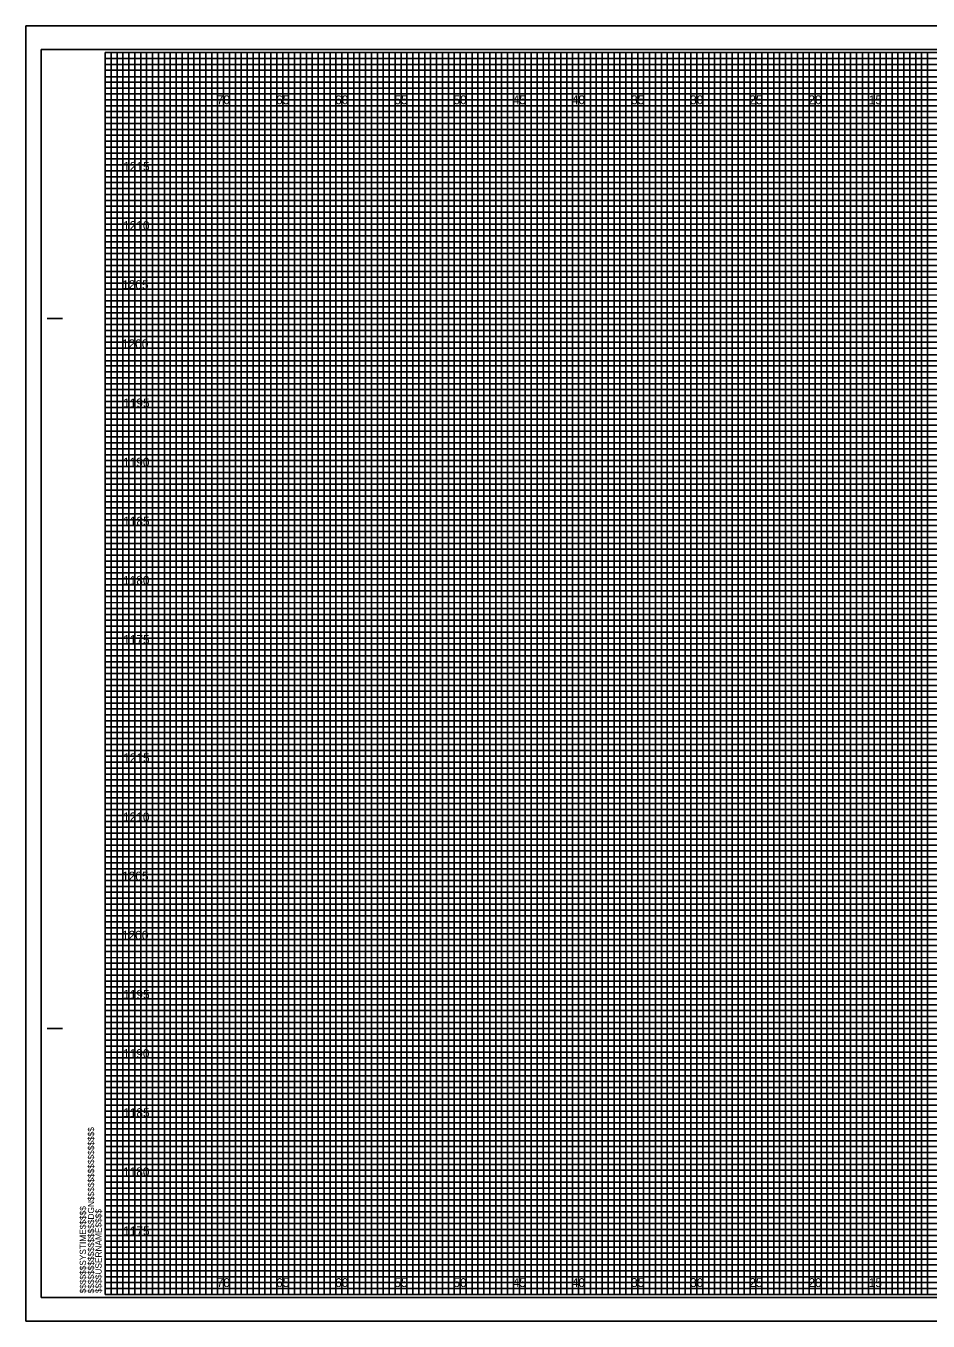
# Model space of a CAD drawing. Extents: x 3478 to 3647, y -9 to 1255.
# Drawn here: x 3478.3 to 3554.6, y 650.7 to 760.2 of the extents above; entities that cross this region are included whole.
import ezdxf

# ---------------------------------------------------------------- set-up
doc = ezdxf.new("R2010")
doc.units = 0
for name, color, linetype in [('Exist Cross Section Cell', 7, 'Continuous'), ('Prop CMT Subgrade Earthwork', 7, 'Continuous'), ('Prop Conc 4in Sidewalk', 7, 'Continuous'), ('Prop Conc Island Cover', 7, 'Continuous'), ('Sheet Cross Section CELL', 7, 'Continuous'), ('Sheet Cross Section Grid Minor 1 CELL', 7, 'Continuous'), ('Sheet Cross Section Grid Minor 2 CELL', 7, 'Continuous'), ('Sheet Cutting Line CELL', 7, 'Continuous'), ('Sheet DOT Grid CELL', 7, 'Continuous'), ('Sheet Plot Border Inside CELL', 7, 'Continuous')]:
    doc.layers.add(name, color=color, linetype=linetype)

msp = doc.modelspace()

# ---------------------------------------------------------------- linework, layer by layer
at = {"layer": 'Exist Cross Section Cell'}
for points in [[(3485.01, 757.97), (3487.51, 757.97), (3487.51, 652.97), (3492.51, 652.97), (3492.51, 757.97), (3497.51, 757.97), (3497.51, 652.97), (3502.51, 652.97), (3502.51, 757.97), (3507.51, 757.97), (3507.51, 652.97), (3512.51, 652.97), (3512.51, 757.97), (3517.51, 757.97), (3517.51, 652.97), (3522.51, 652.97), (3522.51, 757.97), (3527.51, 757.97), (3527.51, 652.97), (3532.51, 652.97), (3532.51, 757.97), (3537.51, 757.97), (3537.51, 652.97), (3542.51, 652.97), (3542.51, 757.97), (3547.51, 757.97), (3547.51, 652.97), (3552.51, 652.97), (3552.51, 757.97), (3557.51, 757.97)], [(3485.01, 755.47), (3622.51, 755.47)], [(3485.01, 745.47), (3645.01, 745.47), (3645.01, 750.47), (3485.01, 750.47)], [(3485.01, 735.47), (3645.01, 735.47), (3645.01, 740.47), (3485.01, 740.47)], [(3485.01, 725.47), (3645.01, 725.47), (3645.01, 730.47), (3485.01, 730.47)], [(3485.01, 715.47), (3645.01, 715.47), (3645.01, 720.47), (3485.01, 720.47)], [(3485.01, 705.47), (3645.01, 705.47), (3645.01, 710.47), (3485.01, 710.47)], [(3485.01, 695.47), (3645.01, 695.47), (3645.01, 700.47), (3485.01, 700.47)], [(3485.01, 685.47), (3645.01, 685.47), (3645.01, 690.47), (3485.01, 690.47)], [(3485.01, 675.47), (3645.01, 675.47), (3645.01, 680.47), (3485.01, 680.47)], [(3485.01, 665.47), (3645.01, 665.47), (3645.01, 670.47), (3485.01, 670.47)], [(3485.01, 655.47), (3645.01, 655.47), (3645.01, 660.47), (3485.01, 660.47)]]:
    msp.add_lwpolyline(points, dxfattribs=at)
at = {"layer": 'Prop CMT Subgrade Earthwork'}
msp.add_lwpolyline([(3478.31, 650.72), (3646.66, 650.72), (3646.66, 760.22), (3478.31, 760.22)], close=True, dxfattribs=at)
at = {"layer": 'Prop Conc 4in Sidewalk'}
for p, q in [((3490.01, 757.97), (3485.01, 757.97)), ((3490.01, 652.97), (3490.01, 757.97)), ((3500.01, 757.97), (3495.01, 757.97)), ((3495.01, 757.97), (3495.01, 652.97)), ((3500.01, 652.97), (3500.01, 757.97)), ((3510.01, 757.97), (3505.01, 757.97)), ((3505.01, 757.97), (3505.01, 652.97)), ((3510.01, 652.97), (3510.01, 757.97)), ((3520.01, 757.97), (3515.01, 757.97)), ((3515.01, 757.97), (3515.01, 652.97)), ((3520.01, 652.97), (3520.01, 757.97)), ((3530.01, 757.97), (3525.01, 757.97)), ((3525.01, 757.97), (3525.01, 652.97)), ((3530.01, 652.97), (3530.01, 757.97)), ((3540.01, 757.97), (3535.01, 757.97)), ((3535.01, 757.97), (3535.01, 652.97)), ((3540.01, 652.97), (3540.01, 757.97)), ((3550.01, 757.97), (3545.01, 757.97)), ((3545.01, 757.97), (3545.01, 652.97)), ((3550.01, 652.97), (3550.01, 757.97)), ((3495.01, 652.97), (3490.01, 652.97)), ((3505.01, 652.97), (3500.01, 652.97)), ((3515.01, 652.97), (3510.01, 652.97)), ((3525.01, 652.97), (3520.01, 652.97)), ((3535.01, 652.97), (3530.01, 652.97)), ((3545.01, 652.97), (3540.01, 652.97)), ((3555.01, 652.97), (3550.01, 652.97))]:
    msp.add_line(p, q, dxfattribs=at)
for points in [[(3485.01, 752.97), (3645.01, 752.97), (3645.01, 747.97), (3485.01, 747.97)], [(3485.01, 742.97), (3645.01, 742.97), (3645.01, 737.97), (3485.01, 737.97)], [(3485.01, 732.97), (3645.01, 732.97), (3645.01, 727.97), (3485.01, 727.97)], [(3485.01, 722.97), (3645.01, 722.97), (3645.01, 717.97), (3485.01, 717.97)], [(3485.01, 712.97), (3645.01, 712.97), (3645.01, 707.97), (3485.01, 707.97)], [(3485.01, 702.97), (3645.01, 702.97), (3645.01, 697.97), (3485.01, 697.97)], [(3485.01, 692.97), (3645.01, 692.97), (3645.01, 687.97), (3485.01, 687.97)], [(3485.01, 682.97), (3645.01, 682.97), (3645.01, 677.97), (3485.01, 677.97)], [(3485.01, 672.97), (3645.01, 672.97), (3645.01, 667.97), (3485.01, 667.97)], [(3485.01, 662.97), (3645.01, 662.97), (3645.01, 657.97), (3485.01, 657.97)]]:
    msp.add_lwpolyline(points, dxfattribs=at)
at = {"layer": 'Sheet Cross Section CELL'}
for p, q in [((3480.11, 735.47), (3481.36, 735.47)), ((3480.16, 735.47), (3481.41, 735.47)), ((3480.11, 675.47), (3481.36, 675.47)), ((3480.16, 675.47), (3481.41, 675.47))]:
    msp.add_line(p, q, dxfattribs=at)
msp.add_lwpolyline([(3645.01, 757.97), (3485.01, 757.97), (3485.01, 652.97), (3645.01, 652.97)], close=True, dxfattribs=at)
at = {"layer": 'Sheet Cross Section Grid Minor 1 CELL'}
for p, q in [((3485.01, 757.47), (3615.01, 757.47)), ((3615.01, 756.96), (3485.01, 756.96)), ((3485.01, 756.96), (3485.01, 756.47)), ((3485.01, 756.47), (3615.01, 756.47)), ((3615.01, 755.92), (3485.01, 755.92)), ((3485.01, 755.92), (3485.01, 754.97)), ((3485.01, 754.97), (3645.01, 754.97))]:
    msp.add_line(p, q, dxfattribs=at)
for points in [[(3485.01, 754.47), (3620.01, 754.47), (3645.01, 754.47), (3645.01, 753.97), (3485.01, 753.97)], [(3485.01, 753.47), (3645.01, 753.47), (3645.01, 752.47), (3485.01, 752.47)], [(3485.01, 751.97), (3645.01, 751.97), (3645.01, 751.47), (3485.01, 751.46)], [(3485.01, 750.97), (3645.01, 750.97), (3645.01, 749.97), (3485.01, 749.97)], [(3485.01, 749.47), (3645.01, 749.47), (3645.01, 748.97), (3485.01, 748.97)], [(3485.01, 748.47), (3645.01, 748.47), (3645.01, 747.47), (3485.01, 747.47)], [(3485.01, 746.97), (3645.01, 746.97), (3645.01, 746.47), (3485.01, 746.47)], [(3485.01, 745.97), (3645.01, 745.97), (3645.01, 744.97), (3485.01, 744.97)], [(3485.01, 744.47), (3645.01, 744.47), (3645.01, 743.97), (3485.01, 743.97)], [(3485.01, 743.47), (3645.01, 743.47), (3645.01, 742.47), (3485.01, 742.47)], [(3485.01, 741.97), (3645.01, 741.97), (3645.01, 741.47), (3485.01, 741.47)], [(3485.01, 740.97), (3645.01, 740.97), (3645.01, 739.95), (3645.01, 739.47), (3645.01, 738.97), (3485.01, 738.97)], [(3485.01, 739.97), (3645.01, 739.97), (3645.01, 739.47), (3485.01, 739.47)], [(3485.01, 738.47), (3645.01, 738.47), (3645.01, 737.47), (3485.01, 737.49)], [(3485.01, 737.49), (3645.01, 737.47), (3645.01, 736.97), (3485.01, 736.97)], [(3485.01, 736.47), (3645.01, 736.47), (3645.01, 735.97), (3485.01, 735.97)], [(3485.01, 734.97), (3645.01, 734.97), (3645.01, 734.47), (3485.01, 734.47)], [(3485.01, 733.97), (3645.01, 733.97), (3645.01, 733.47), (3485.01, 733.47)], [(3484.97, 732.42), (3645.01, 732.42), (3645.01, 731.91), (3484.97, 731.91)], [(3485.01, 731.47), (3645.01, 731.47), (3645.01, 730.97), (3485.01, 730.97)], [(3485.01, 729.97), (3645.01, 729.97), (3645.01, 729.47), (3485.01, 729.47)], [(3485.01, 728.97), (3645.01, 728.97), (3645.01, 728.47), (3485.01, 728.47)], [(3485.01, 727.47), (3645.01, 727.47), (3645.01, 726.97), (3485.01, 726.97)], [(3485.01, 726.47), (3645.01, 726.47), (3645.01, 725.97), (3485.01, 725.97)], [(3485.01, 724.97), (3645.01, 724.97), (3645.01, 724.47), (3485.01, 724.47)], [(3485.01, 723.97), (3645.01, 723.97), (3645.01, 723.47), (3485.01, 723.47)], [(3485.01, 722.47), (3645.01, 722.47), (3645, 721.96), (3485.01, 721.97)], [(3485.01, 721.47), (3645.01, 721.47), (3645.01, 720.97), (3485.01, 720.97)], [(3485.01, 719.97), (3645.01, 719.97), (3645.01, 719.47), (3485.01, 719.47)], [(3485.01, 718.97), (3645.01, 718.97), (3645.01, 718.47), (3485.01, 718.47)], [(3485.01, 717.47), (3645.01, 717.47), (3645.01, 716.97), (3485.01, 716.97)], [(3485.01, 716.47), (3645.01, 716.47), (3645.01, 715.97), (3485.01, 715.97)], [(3485.01, 714.97), (3645.01, 714.97), (3645.01, 714.47), (3485.01, 714.47)], [(3485.01, 713.97), (3645.01, 713.97), (3645.01, 713.47), (3485.01, 713.47)], [(3485.01, 712.47), (3645.01, 712.47), (3645.01, 711.97), (3485.01, 711.97)], [(3485.01, 711.47), (3645.04, 711.43), (3645.01, 710.97), (3485.01, 710.97)], [(3485.01, 709.97), (3645.01, 709.97), (3645.01, 709.47), (3485.01, 709.47)], [(3485.01, 708.97), (3645.01, 708.97), (3645.01, 708.47), (3485.01, 708.47)], [(3485.01, 707.47), (3645.01, 707.47), (3645.01, 706.97), (3485.01, 706.97)], [(3485.01, 706.47), (3645.01, 706.47), (3645.01, 705.97), (3485.01, 705.97)], [(3485.01, 704.97), (3645.01, 704.97), (3645.01, 704.47), (3485.01, 704.47)], [(3485.01, 703.97), (3645.01, 703.97), (3645.01, 703.47), (3485.01, 703.47)], [(3485.01, 702.47), (3645.01, 702.47), (3645.01, 701.97), (3485.01, 701.97)], [(3485.01, 701.47), (3645.01, 701.47), (3645.01, 700.97), (3485.01, 700.97)], [(3485.01, 699.97), (3645.01, 699.97), (3645.01, 699.47), (3485.01, 699.47)], [(3485.01, 698.97), (3645.01, 698.97), (3645.01, 698.47), (3485.01, 698.47)], [(3485.01, 697.47), (3645.01, 697.47), (3645.01, 696.97), (3485.01, 696.97)], [(3485.01, 696.47), (3645.01, 696.47), (3645.01, 695.97), (3485.01, 695.97)], [(3485.01, 694.97), (3645.01, 694.97), (3645.01, 694.47), (3485.01, 694.47)], [(3485.01, 693.97), (3645.01, 693.97), (3645.01, 693.47), (3485.01, 693.47)], [(3485.01, 692.47), (3645.01, 692.47), (3645, 691.96), (3485.01, 691.97)], [(3485.01, 691.47), (3645.01, 691.47), (3645.01, 690.97), (3485.01, 690.97)], [(3485.01, 689.97), (3645.01, 689.97), (3645.01, 689.47), (3485.01, 689.47)], [(3485.01, 688.97), (3645.01, 688.97), (3645.01, 688.47), (3485.01, 688.47)], [(3485.01, 687.47), (3645.01, 687.47), (3645.01, 686.97), (3485.01, 686.97)], [(3485.01, 686.47), (3645.01, 686.47), (3645.01, 685.97), (3485.01, 685.97)], [(3485.01, 684.97), (3645.01, 684.97), (3645.01, 684.47), (3485.01, 684.47)], [(3485.01, 683.97), (3645.01, 683.97), (3645.01, 683.47), (3485.01, 683.47)], [(3485.01, 682.47), (3645.01, 682.47), (3645.01, 681.97), (3485.01, 681.97)], [(3485.01, 681.47), (3645.04, 681.43), (3645.01, 680.97), (3485.01, 680.97)], [(3485.01, 679.97), (3645.01, 679.97), (3645.01, 679.47), (3485.01, 679.47)], [(3485.01, 678.97), (3645.01, 678.97), (3645.01, 678.47), (3485.01, 678.47)], [(3485.01, 677.47), (3645.01, 677.47), (3645.01, 676.97), (3485.01, 676.97)], [(3485.01, 676.47), (3645.01, 676.47), (3645.01, 675.97), (3485.01, 675.97)], [(3485.01, 674.97), (3645.01, 674.97), (3645.01, 674.47), (3485.01, 674.47)], [(3485.01, 673.97), (3645.01, 673.97), (3645.01, 673.47), (3485.01, 673.47)], [(3485.01, 672.47), (3645.01, 672.47), (3645.01, 671.97), (3485.01, 671.97)], [(3485.01, 671.47), (3645.01, 671.47), (3645.01, 670.97), (3485.01, 670.97)], [(3485.01, 669.97), (3645.01, 669.97), (3645.01, 669.47), (3485.01, 669.47)], [(3485.01, 668.97), (3645.01, 668.97), (3645.01, 668.47), (3485.01, 668.47)], [(3485.01, 667.47), (3645.01, 667.47), (3645.01, 666.97), (3485.01, 666.97)], [(3485.01, 666.47), (3645.01, 666.47), (3645.01, 665.97), (3485.01, 665.97)], [(3485.01, 664.97), (3645.01, 664.97), (3645.01, 664.47), (3485.01, 664.47)], [(3485.01, 663.97), (3645.01, 663.97), (3645.01, 663.47), (3485.01, 663.47)], [(3485.01, 662.47), (3645.01, 662.47), (3645.01, 661.97), (3485.01, 661.97)], [(3485.01, 661.47), (3645.01, 661.47), (3645.01, 660.97), (3485.01, 660.97)], [(3485.01, 659.97), (3645.01, 659.97), (3645.01, 659.47), (3485.01, 659.47)], [(3485.01, 658.97), (3645.01, 658.97), (3645.01, 658.47), (3485.01, 658.47)], [(3485.01, 657.47), (3645.01, 657.47), (3645.01, 656.97), (3485.01, 656.97)], [(3485.01, 656.47), (3645.01, 656.47), (3645.01, 655.97), (3485.01, 655.97)], [(3485.01, 654.97), (3645.01, 654.97), (3645.01, 654.47), (3485.01, 654.47)], [(3485.01, 653.97), (3645.01, 653.97), (3645.01, 653.47), (3485.01, 653.47)]]:
    msp.add_lwpolyline(points, dxfattribs=at)
at = {"layer": 'Sheet Cross Section Grid Minor 2 CELL'}
for points in [[(3485.01, 652.97), (3485.51, 652.97), (3485.51, 757.97), (3486.01, 757.97), (3486.01, 652.97)], [(3486.01, 652.97), (3486.51, 652.97), (3486.51, 757.97), (3487.01, 757.97), (3487.01, 652.97)], [(3487.51, 652.97), (3488.01, 652.97), (3488.01, 757.97), (3488.51, 757.97), (3488.51, 652.97)], [(3488.51, 652.97), (3489.01, 652.97), (3489.01, 757.97), (3489.51, 757.97), (3489.51, 652.97)], [(3490.01, 652.97), (3490.51, 652.97), (3490.51, 757.97), (3491.01, 757.97), (3491.01, 652.97)], [(3491.01, 652.97), (3491.51, 652.97), (3491.51, 757.97), (3492.01, 757.97), (3492.01, 652.97)], [(3492.51, 652.97), (3493.01, 652.97), (3493.01, 757.97), (3493.51, 757.97), (3493.51, 652.97)], [(3493.51, 652.97), (3494.01, 652.97), (3494.01, 757.97), (3494.51, 757.97), (3494.51, 652.97)], [(3495.01, 652.97), (3495.51, 652.97), (3495.51, 757.97), (3496.01, 757.97), (3496.01, 652.97)], [(3496.01, 652.97), (3496.51, 652.97), (3496.51, 757.97), (3497.01, 757.97), (3497.01, 652.97)], [(3497.51, 652.97), (3498.01, 652.97), (3498.01, 757.97), (3498.51, 757.97), (3498.51, 652.97)], [(3498.51, 652.97), (3499.01, 652.97), (3499.01, 757.97), (3499.51, 757.97), (3499.51, 652.97)], [(3500.01, 652.97), (3500.51, 652.97), (3500.51, 757.97), (3501.01, 757.97), (3501.01, 652.97)], [(3501.01, 652.97), (3501.51, 652.97), (3501.51, 757.97), (3502.01, 757.97), (3502.01, 652.97)], [(3502.51, 652.97), (3503.01, 652.97), (3503.01, 757.97), (3503.51, 757.97), (3503.51, 652.97)], [(3503.51, 652.97), (3504.01, 652.97), (3504.01, 757.97), (3504.51, 757.97), (3504.51, 652.97)], [(3505.01, 652.97), (3505.51, 652.97), (3505.51, 757.97), (3506.01, 757.97), (3506.01, 652.97)], [(3506.01, 652.97), (3506.51, 652.97), (3506.51, 757.97), (3507.01, 757.97), (3507.01, 652.97)], [(3507.51, 652.97), (3508.01, 652.97), (3508.01, 757.97), (3508.51, 757.97), (3508.51, 652.97)], [(3508.51, 652.97), (3509.01, 652.97), (3509.01, 757.97), (3509.51, 757.97), (3509.51, 652.97)], [(3510.01, 652.97), (3510.51, 652.97), (3510.51, 757.97), (3511.01, 757.97), (3511.01, 652.97)], [(3511.01, 652.97), (3511.51, 652.97), (3511.51, 757.97), (3512.01, 757.97), (3512.01, 652.97)], [(3512.51, 652.97), (3513.01, 652.97), (3513.01, 757.97), (3513.51, 757.97), (3513.51, 652.97)], [(3513.51, 652.97), (3514.01, 652.97), (3514.01, 757.97), (3514.51, 757.97), (3514.51, 652.97)], [(3515.01, 652.97), (3515.51, 652.97), (3515.51, 757.97), (3516.01, 757.97), (3516.01, 652.97)], [(3516.01, 652.97), (3516.51, 652.97), (3516.51, 757.97), (3517.01, 757.97), (3517.01, 652.97)], [(3517.51, 652.97), (3518.01, 652.97), (3518.01, 757.97), (3518.51, 757.97), (3518.51, 652.97)], [(3518.51, 652.97), (3519.01, 652.97), (3519.01, 757.97), (3519.51, 757.97), (3519.51, 652.97)], [(3520.01, 652.97), (3520.51, 652.97), (3520.51, 757.97), (3521.01, 757.97), (3521.01, 652.97)], [(3521.01, 652.97), (3521.51, 652.97), (3521.51, 757.97), (3522.01, 757.97), (3522.01, 652.97)], [(3522.51, 652.97), (3523.01, 652.97), (3523.01, 757.97), (3523.51, 757.97), (3523.51, 652.97)], [(3523.51, 652.97), (3524.01, 652.97), (3524.01, 757.97), (3524.51, 757.97), (3524.51, 652.97)], [(3525.01, 652.97), (3525.51, 652.97), (3525.51, 757.97), (3526.01, 757.97), (3526.01, 652.97)], [(3526.01, 652.97), (3526.51, 652.97), (3526.51, 757.97), (3527.01, 757.97), (3527.01, 652.97)], [(3527.51, 652.97), (3528.01, 652.97), (3528.01, 757.97), (3528.51, 757.97), (3528.51, 652.97)], [(3528.51, 652.97), (3529.01, 652.97), (3529.01, 757.97), (3529.51, 757.97), (3529.51, 652.97)], [(3530.01, 652.97), (3530.51, 652.97), (3530.51, 757.97), (3531.01, 757.97), (3531.01, 652.97)], [(3531.01, 652.97), (3531.51, 652.97), (3531.51, 757.97), (3532.01, 757.97), (3532.01, 652.97)], [(3532.51, 652.97), (3533.01, 652.97), (3533.01, 757.97), (3533.51, 757.97), (3533.51, 652.97)], [(3533.51, 652.97), (3534.01, 652.97), (3534.01, 757.97), (3534.51, 757.97), (3534.51, 652.97)], [(3535.01, 652.97), (3535.51, 652.97), (3535.51, 757.97), (3536.01, 757.97), (3536.01, 652.97)], [(3536.01, 652.97), (3536.51, 652.97), (3536.51, 757.97), (3537.01, 757.97), (3537.01, 652.97)], [(3537.51, 652.97), (3538.01, 652.97), (3538.01, 757.97), (3538.51, 757.97), (3538.51, 652.97)], [(3538.51, 652.97), (3539.01, 652.97), (3539.01, 757.97), (3539.51, 757.97), (3539.51, 652.97)], [(3540.01, 652.97), (3540.51, 652.97), (3540.51, 757.97), (3541.01, 757.97), (3541.01, 652.97)], [(3541.01, 652.97), (3541.51, 652.97), (3541.51, 757.97), (3542.01, 757.97), (3542.01, 652.97)], [(3542.51, 652.97), (3543.01, 652.97), (3543.01, 757.97), (3543.51, 757.97), (3543.51, 652.97)], [(3543.51, 652.97), (3544.01, 652.97), (3544.01, 757.97), (3544.51, 757.97), (3544.51, 652.97)], [(3545.01, 652.97), (3545.51, 652.97), (3545.51, 757.97), (3546.01, 757.97), (3546.01, 652.97)], [(3546.01, 652.97), (3546.51, 652.97), (3546.51, 757.97), (3547.01, 757.97), (3547.01, 652.97)], [(3547.51, 652.97), (3548.01, 652.97), (3548.01, 757.97), (3548.51, 757.97), (3548.51, 652.97)], [(3548.51, 652.97), (3549.01, 652.97), (3549.01, 757.97), (3549.51, 757.97), (3549.51, 652.97)], [(3550.01, 652.97), (3550.51, 652.97), (3550.51, 757.97), (3551.01, 757.97), (3551.01, 652.97)], [(3551.01, 652.97), (3551.51, 652.97), (3551.51, 757.97), (3552.01, 757.97), (3552.01, 652.97)], [(3552.51, 652.97), (3553.01, 652.97), (3553.01, 757.97), (3553.51, 757.97), (3553.51, 652.97)], [(3553.51, 652.97), (3554.01, 652.97), (3554.01, 757.97), (3554.51, 757.97), (3554.51, 652.97)]]:
    msp.add_lwpolyline(points, dxfattribs=at)
at = {"layer": 'Sheet Cutting Line CELL'}
for p, q in [((3646.66, 760.22), (3478.31, 760.22)), ((3478.31, 760.22), (3478.31, 650.72)), ((3478.31, 650.72), (3646.66, 650.72))]:
    msp.add_line(p, q, dxfattribs=at)
at = {"layer": 'Sheet DOT Grid CELL'}
for p, q in [((3490.01, 652.97), (3490.01, 757.97)), ((3495.01, 652.97), (3495.01, 757.97)), ((3500.01, 652.97), (3500.01, 757.97)), ((3505.01, 652.97), (3505.01, 757.97)), ((3510.01, 652.97), (3510.01, 757.97)), ((3515.01, 652.97), (3515.01, 757.97)), ((3520.01, 652.97), (3520.01, 757.97)), ((3525.01, 652.97), (3525.01, 757.97)), ((3530.01, 652.97), (3530.01, 757.97)), ((3535.01, 652.97), (3535.01, 757.97)), ((3540.01, 652.97), (3540.01, 757.97)), ((3545.01, 652.97), (3545.01, 757.97)), ((3550.01, 652.97), (3550.01, 757.97)), ((3485.01, 752.97), (3645.01, 752.97)), ((3485.01, 747.97), (3645.01, 747.97)), ((3485.01, 742.97), (3645.01, 742.97)), ((3485.01, 737.97), (3645.01, 737.97)), ((3485.01, 732.97), (3645.01, 732.97)), ((3485.01, 727.97), (3645.01, 727.97)), ((3485.01, 722.97), (3645.01, 722.97)), ((3485.01, 717.97), (3645.01, 717.97)), ((3485.01, 712.97), (3645.01, 712.97)), ((3485.01, 707.97), (3645.01, 707.97)), ((3485.01, 702.97), (3645.01, 702.97)), ((3485.01, 697.97), (3645.01, 697.97)), ((3485.01, 692.97), (3645.01, 692.97)), ((3485.01, 687.97), (3645.01, 687.97)), ((3485.01, 682.97), (3645.01, 682.97)), ((3485.01, 677.97), (3645.01, 677.97)), ((3485.01, 672.97), (3645.01, 672.97)), ((3485.01, 667.97), (3645.01, 667.97)), ((3485.01, 662.97), (3645.01, 662.97)), ((3485.01, 657.97), (3645.01, 657.97))]:
    msp.add_line(p, q, dxfattribs=at)
at = {"layer": 'Sheet Plot Border Inside CELL'}
msp.add_lwpolyline([(3479.61, 652.72), (3646.21, 652.72), (3646.21, 758.22), (3479.61, 758.22)], close=True, dxfattribs=at)

# ---------------------------------------------------------------- texts
at = {"layer": 'Prop Conc Island Cover'}
for s, p in [('70', (3494.44, 753.6)), ('65', (3499.45, 753.6)), ('60', (3504.44, 753.6)), ('55', (3509.45, 753.6)), ('50', (3514.44, 753.6)), ('45', (3519.45, 753.6)), ('40', (3524.44, 753.6)), ('35', (3529.45, 753.6)), ('30', (3534.44, 753.6)), ('25', (3539.45, 753.6)), ('20', (3544.44, 753.6)), ('15', (3549.54, 753.6)), ('1215', (3486.53, 747.97)), ('1210', (3486.52, 742.97)), ('1205', (3486.44, 737.97)), ('1200', (3486.43, 732.97)), ('1195', (3486.53, 727.97)), ('1190', (3486.52, 722.97)), ('1185', (3486.53, 717.97)), ('1180', (3486.52, 712.97)), ('1175', (3486.53, 707.97)), ('1215', (3486.53, 697.97)), ('1210', (3486.52, 692.97)), ('1205', (3486.44, 687.97)), ('1200', (3486.43, 682.97)), ('1195', (3486.53, 677.97)), ('1190', (3486.52, 672.97)), ('1185', (3486.53, 667.97)), ('1180', (3486.52, 662.97)), ('1175', (3486.53, 657.97)), ('70', (3494.44, 653.6)), ('65', (3499.45, 653.6)), ('60', (3504.44, 653.6)), ('55', (3509.45, 653.6)), ('50', (3514.44, 653.6)), ('45', (3519.45, 653.6)), ('40', (3524.44, 653.6)), ('35', (3529.45, 653.6)), ('30', (3534.44, 653.6)), ('25', (3539.45, 653.6)), ('20', (3544.44, 653.6)), ('15', (3549.54, 653.6))]:
    msp.add_text(s, height=0.75, dxfattribs=at).set_placement(p)
at = {"layer": 'Sheet Cross Section CELL'}
for s, p in [('$$$$$$$$$$$$$$$$DGN$$$$$$$$$$$$$$$$', (3484.07, 653.06)), ('$$$$$$SYSTIME$$$$$', (3483.38, 653.06)), ('$$$$USERNAME$$$$', (3484.7, 653.09))]:
    msp.add_text(s, height=0.525, rotation=90, dxfattribs=at).set_placement(p)

doc.saveas('drawing.dxf')
